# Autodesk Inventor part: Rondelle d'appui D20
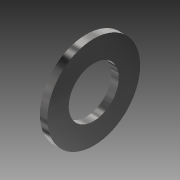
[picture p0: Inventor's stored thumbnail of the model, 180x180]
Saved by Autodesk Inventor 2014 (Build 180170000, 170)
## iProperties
Created: 2015-09
Part Number: Rondelle d'appui D20
Material: Générique
Document SubType Name: Modeling
Designer: OL
Density: 1 g/cm^3
Appearance: Par défaut
Author: OL
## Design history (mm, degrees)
sketch "Esquisse1"
  geometry: C1 r 18.5 at (0, 0); C2 r 10 at (0, 0); 1 further point
  constraints: 2 centre point, 2 coincident
  dimensions: "d0" = 20 diameter of C2; "d3" = 37 diameter of C1
extrude "Extrusion1" new body sketch "Esquisse1" distance "d4" = 3; taper "d5" = 0 deg
node "Solide1"
